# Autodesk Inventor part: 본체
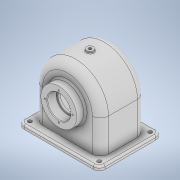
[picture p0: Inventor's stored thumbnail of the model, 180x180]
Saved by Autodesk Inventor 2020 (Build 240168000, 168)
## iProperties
Created: 2022-09
Part Number: 본체
Material: 일반
Document SubType Name: Modeling
Designer: Administrator
Density: 1 g/cm^3
Appearance: 기본값
Author: Administrator
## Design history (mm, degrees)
sketch "스케치1"
  geometry: L1 (70, -54)-(-70, -54); L2 (-70, -54)-(-70, 54); L3 (-70, 54)-(70, 54); L4 (70, 54)-(70, -54); L5 (70, -54)-(-70, 54); L6 (-70, -54)-(70, 54); 1 further point
  constraints: 12 end point, 2 midpoint, 2 parallel, 1 horizontal, 1 perpendicular
  dimensions: "d0" = 140 distance of L2.end L3.end; "d1" = 108 distance of L1.end L2.end
extrude "돌출1" new body sketch "스케치1" distance "d2" = 7; taper "d3" = 0 deg
sketch "스케치2"
  geometry: L1 (70, 0)-(-70, 0) reference; L2 (57, 64)-(57, 3); L3 (-57, 64)-(-57, 3); L4 (-70, 7)-(70, 7) reference; A1 r 57 centre (0, 64) between (57, 64) and (-57, 64); 3 further points
  constraints: 4 end point, 2 point on circle, 2 tangent, 2 vertical, 1 centre point, 1 vertical alignment
  dimensions: "d4" = 114 diameter of A1; "d5" = 64 distance from line of L1 A1.centre
extrude "돌출2" new body sketch "스케치2" stored distance "d6" = 78; taper "d7" = 0 deg
fillet "모깎기1" dims "d8" = 14
feature "쉘1" dims "d9" = 5
sketch "스케치3"
  geometry: L1 (-43, -39)-(43, -39) reference; L2 (57, -25)-(-57, -25) reference; L3 (-57, 25)-(57, 25) reference; L4 (-57, 25)-(-57, -25) reference; L5 (57, -25)-(-57, -25) reference; L6 (57, 25)-(57, -25) reference; L7 (43, 39)-(-43, 39) reference; L8 (-57, 25)-(57, 25) reference; L9 (-43, 34)-(43, 34) reference; L10 (-52, 25)-(-52, -25) reference; L11 (43, -34)-(-43, -34) reference; L12 (52, 25)-(52, -25) reference; A1 r 14 centre (-43, -25) between (-57, -25) and (-43, -39) reference; A2 r 14 centre (43, -25) between (43, -39) and (57, -25) reference; A3 r 14 centre (43, 25) between (57, 25) and (43, 39) reference; A4 r 14 centre (-43, 25) between (-43, 39) and (-57, 25) reference; A5 r 9 centre (-43, -25) between (-52, -25) and (-43, -34) reference; A6 r 9 centre (-43, 25) between (-43, 34) and (-52, 25) reference; A7 r 9 centre (43, -25) between (43, -34) and (52, -25) reference; A8 r 9 centre (43, 25) between (52, 25) and (43, 34) reference; 1 further point
extrude "돌출3" cut sketch "스케치3" distance "d10" = 78; taper "d11" = 0 deg
feature "결합1"
  node "솔리드2"
sketch "스케치4"
  geometry: L1 (64, -73)-(64, 93); L2 (0, 54)-(0, -54) reference; L3 (84, -34)-(84, -20); L4 (92, -20)-(100.083, -34); L5 (107, -34)-(64, -34) reference; L6 (92, -20)-(84, -20); L7 (95, 39)-(95, 54); L8 (95, 54)-(64, 54); L9 (64, 39)-(107, 39) reference; 1 further point
  constraints: 12 end point, 4 point on line, 3 vertical, 2 perpendicular, 1 horizontal
  dimensions: "d12" = 64 distance between parallel lines of L2 L1; "d13" = 60 deg angle of L5 L4; "d14" = 40 diameter of L3 L1; "d15" = 14 distance between parallel lines of L6 L5; "d16" = 56 diameter of L4.start L1; "d17" = 15 distance between parallel lines of L8 L9; "d18" = 62 diameter of L7 L1
revolve "회전1" sketch "스케치4" stored, may be unused: angle "d19" = 90 deg
sketch "스케치5"
  geometry: A1 r 57 centre (0, 0) between (57, 0) and (-57, 0) reference; 2 further points
  constraints: 1 coincident
hole "구멍1" sketch "스케치5" at (0, 0) diameter "d20" = 40; stored, may be unused: countersink angle "d24" = 90 deg, drill point angle "d26" = 0 deg; dims "d21" = 6, "d22" = 64, "d23" = 3, "d25" = 16
sketch "스케치6"
  geometry: C1 r 31 at (0, 0) reference; 2 further points
  constraints: 1 coincident
hole "구멍2" sketch "스케치6" at (0, 0) diameter "d27" = 35; stored, may be unused: countersink angle "d31" = 90 deg, drill point angle "d33" = 0 deg; dims "d28" = 6, "d29" = 40, "d30" = 16, "d32" = 5
node "작업 평면1"
sketch "스케치7"
  geometry: C1 r 6 at (0, 0); 1 further point
  constraints: 1 centre point, 1 coincident
  dimensions: "d35" = 12 diameter of C1
extrude "돌출4" join sketch "스케치7" stored distance "d36" = 78; taper "d37" = 0 deg
sketch "스케치8"
  geometry: C1 r 6 at (0, 0) reference; 2 further points
  constraints: 1 coincident
hole "구멍3" sketch "스케치8" at (0, 0) diameter "d38" = 5.1881; stored, may be unused: countersink angle "d42" = 90 deg, drill point angle "d44" = 0 deg; dims "d39" = 12, "d40" = 40, "d41" = 16, "d43" = 16
fillet "모깎기2" dims "d45" = 10
sketch "스케치9"
  geometry: A1 r 10 centre (60, 44) between (70, 44) and (60, 54) reference; A2 r 10 centre (60, -44) between (60, -54) and (70, -44) reference; A3 r 10 centre (-60, -44) between (-70, -44) and (-60, -54) reference; A4 r 10 centre (-60, 44) between (-60, 54) and (-70, 44) reference; 5 further points
  constraints: 4 coincident
hole "구멍4" sketch "스케치9" at (60, 44), (60, -44), (-60, -44), (-60, 44) diameter "d46" = 6.6; stored, may be unused: countersink angle "d50" = 90 deg, drill point angle "d52" = 0 deg; dims "d47" = 12, "d48" = 40, "d49" = 16, "d51" = 16
chamfer "모따기1" distance "d53" = 1; stored, may be unused: second distance "d54" = 2, angle "d55" = 45 deg
fillet "모깎기3" dims "d56" = 0.6
fillet "모깎기4" dims "d57" = 3, "d84" = 1
sketch "스케치10"
  geometry: L1 (-14, 57)-(-14, 0) reference; L2 (-19, -7)-(-29, -7) reference; 2 further points
  constraints: 1 other
  dimensions: "d58" = 39 distance from line of L1 point (25, 10); "d59" = 17 distance from line of L2 point (25, 10)
feature "엠보싱1" sketch "스케치10" dims "d0" = 140, "d1" = 108, "d60" = 0.5, "d61" = 0
sketch "스케치11" dims "d62" = 48
  geometry: C1 r 31 at (0, 0) reference; C2 r 21 at (0, 0) reference; 3 further points
  constraints: 2 vertical alignment, 1 coincident, 2 other
hole "구멍5" sketch "스케치11" at (0, 24) diameter "d63" = 2.459; stored, may be unused: countersink angle "d67" = 90 deg, drill point angle "d69" = 118 deg; dims "d64" = 7, "d65" = 40, "d66" = 16, "d68" = 9
sketch "스케치12" dims "d73" = 48
  geometry: C1 r 32 at (0, 0) reference; C2 r 21 at (0, 0) reference; 3 further points
  constraints: 2 vertical alignment, 1 coincident, 2 other
hole "구멍6" sketch "스케치12" at (0, 24) diameter "d74" = 2.459; stored, may be unused: countersink angle "d78" = 90 deg, drill point angle "d80" = 118 deg; dims "d75" = 7, "d76" = 40, "d77" = 16, "d79" = 9
node "솔리드1"
pattern_circular "원형 패턴1" dims angle "d71" = 360 deg
pattern_circular "원형 패턴2" dims angle "d82" = 360 deg
node "투영된 루프1"
node "투영된 루프2"
node "투영된 루프3"
feature "A9D066F2-1C7D-4E18-AEED-F7BC21143FA4" dims "d20" = 40, "d21" = 6, "d22" = 64, "d23" = 3, "d24" = 90 deg, "d25" = 16, "d26" = 0
other parameters: "d34" = 124
